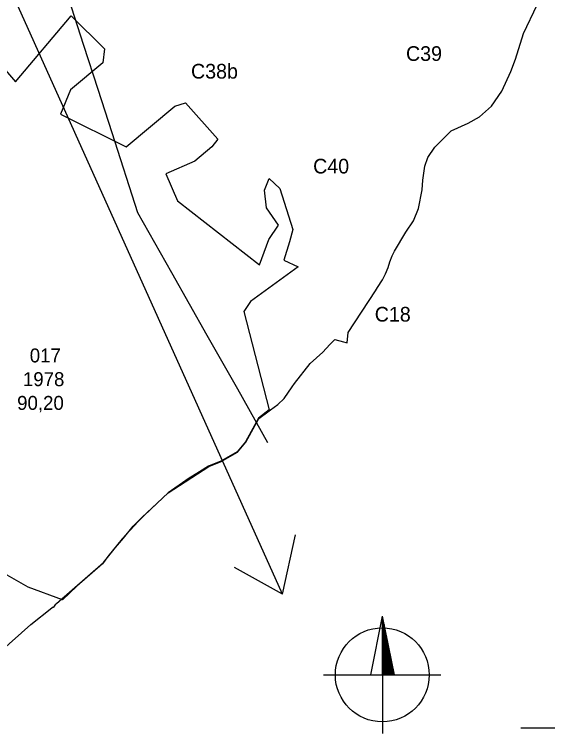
# Model space of a CAD drawing. Extents: x -557103 to -548162, y -1041918 to -1033974.
# Drawn here: x -552210 to -551120, y -1038919 to -1037449 of the extents above; entities that cross this region are included whole.
import ezdxf

# ---------------------------------------------------------------- set-up
doc = ezdxf.new("R2010")
doc.units = 0
for name, color, linetype in [('body3', 7, 'Continuous'), ('Vrstva 14', 7, 'Continuous'), ('Vrstva 15', 7, 'Continuous'), ('Vrstva 37', 7, 'Continuous'), ('Vrstva 48', 7, 'Continuous'), ('Vrstva 57', 7, 'Continuous'), ('Vrstva 9', 7, 'Continuous')]:
    doc.layers.add(name, color=color, linetype=linetype)

msp = doc.modelspace()

# ---------------------------------------------------------------- linework, layer by layer
at = {"layer": 'body3'}
for p, q in [((-551169.3, -1037488.5), (-551141.4, -1037429.8)), ((-551185.4, -1037540.5), (-551169.3, -1037488.5)), ((-551194.9, -1037566.1), (-551185.4, -1037540.5)), ((-551213.2, -1037606.2), (-551194.9, -1037566.1)), ((-551234.2, -1037636.8), (-551213.2, -1037606.2)), ((-551259, -1037658.6), (-551234.2, -1037636.8)), ((-551282, -1037671.4), (-551259, -1037658.6)), ((-551317, -1037686.9), (-551282, -1037671.4)), ((-551350.7, -1037720.5), (-551317, -1037686.9)), ((-551364.5, -1037741.5), (-551350.7, -1037720.5)), ((-551370.6, -1037759.1), (-551364.5, -1037741.5)), ((-551374.7, -1037788.2), (-551370.6, -1037759.1)), ((-551376.2, -1037807.5), (-551374.7, -1037788.2)), ((-551383.6, -1037845.9), (-551376.2, -1037807.5)), ((-551394.1, -1037870.8), (-551383.6, -1037845.9)), ((-551409.7, -1037894), (-551394.1, -1037870.8)), ((-551432.9, -1037932.8), (-551409.7, -1037894)), ((-551437.9, -1037942.3), (-551432.9, -1037932.8)), ((-551445.9, -1037966.2), (-551442.4, -1037954.6)), ((-551442.4, -1037954.6), (-551437.9, -1037942.3)), ((-551451, -1037979.2), (-551445.9, -1037966.2)), ((-551457.2, -1037991.7), (-551451, -1037979.2)), ((-551467.5, -1038007.5), (-551457.2, -1037991.7)), ((-551527.6, -1038099.2), (-551471.9, -1038014.2)), ((-551471.9, -1038014.2), (-551467.5, -1038007.5)), ((-551529.5, -1038120.2), (-551527.6, -1038099.2)), ((-551564.9, -1038123.8), (-551555.1, -1038113.1)), ((-551555.1, -1038113.1), (-551537.3, -1038118)), ((-551537.3, -1038118), (-551532.3, -1038119.4)), ((-551579.4, -1038139.6), (-551564.9, -1038123.8)), ((-551532.3, -1038119.4), (-551529.5, -1038120.2)), ((-551605.4, -1038162.3), (-551579.4, -1038139.6)), ((-551637.2, -1038203.1), (-551605.4, -1038162.3)), ((-551642, -1038210), (-551637.2, -1038203.1)), ((-551658.3, -1038233.8), (-551642, -1038210)), ((-551671.5, -1038246.1), (-551658.3, -1038233.8)), ((-551686.3, -1038257.1), (-551671.5, -1038246.1)), ((-551710.1, -1038274.8), (-551691.9, -1038261.2)), ((-551691.9, -1038261.2), (-551686.3, -1038257.1)), ((-551737, -1038322.9), (-551710.1, -1038274.8)), ((-551753.8, -1038343.5), (-551737, -1038322.9)), ((-551787.2, -1038362.5), (-551753.8, -1038343.5)), ((-551812.7, -1038372.6), (-551787.2, -1038362.5)), ((-551895.6, -1038427), (-551812.7, -1038372.6)), ((-551918.3, -1038448), (-551895.6, -1038427)), ((-551959.9, -1038487.4), (-551918.3, -1038448)), ((-551987.1, -1038519.1), (-551967.4, -1038494.5)), ((-551967.4, -1038494.5), (-551959.9, -1038487.4)), ((-552003.2, -1038538.4), (-551987.1, -1038519.1)), ((-552027.9, -1038569), (-552003.2, -1038538.4)), ((-552124, -1038652.6), (-552027.9, -1038569)), ((-552176.5, -1038695.8), (-552133.3, -1038661.8)), ((-552133.3, -1038661.8), (-552130.6, -1038659.6)), ((-552130.6, -1038659.6), (-552129.5, -1038660.1)), ((-552129.5, -1038660.1), (-552125.2, -1038654.1)), ((-552125.2, -1038654.1), (-552124, -1038652.6)), ((-552240.3, -1038752.1), (-552176.5, -1038695.8))]:
    msp.add_line(p, q, dxfattribs=at)
at = {"layer": 'Vrstva 14'}
for q in [(-551635.1, -1038512.8), (-551760.2, -1038579.1)]:
    msp.add_line((-551661.8, -1038633.9), q, dxfattribs=at)
msp.add_lwpolyline([(-551661.8, -1038633.9), (-553519.6, -1034507.2), (-553504.9, -1034676.5)], dxfattribs=at)
at = {"layer": 'Vrstva 15'}
for points in [[(-552068.1, -1037512.6), (-552118.7, -1037355.6), (-552166.5, -1037207.2), (-552210.9, -1037069.8), (-552249.3, -1036951.7), (-552280.1, -1036856.3), (-552310.8, -1036764.1)], [(-551691.6, -1038324.2), (-551753.3, -1038215.2), (-551815.6, -1038104.9), (-551888, -1037977.1), (-551957.3, -1037854.4), (-552010.3, -1037691.4), (-552039, -1037602.4), (-552068.1, -1037512.6)]]:
    msp.add_lwpolyline(points, dxfattribs=at)
at = {"layer": 'Vrstva 48'}
msp.add_line((-551174.3, -1038906.8), (-550963.1, -1038906.8), dxfattribs=at)
at = {"layer": 'Vrstva 57'}
for p, q in [((-551457.9, -1038678.6), (-551481.8, -1038798.6)), ((-551457.9, -1038678.6), (-551457.7, -1038918.6)), ((-551457.9, -1038678.6), (-551433.8, -1038798.6)), ((-551456.7, -1038683.8), (-551456.6, -1038798.6)), ((-551455.5, -1038690.9), (-551455.4, -1038798.6)), ((-551454.3, -1038695.8), (-551454.2, -1038798.6)), ((-551453.1, -1038702.9), (-551453, -1038798.6)), ((-551451.9, -1038708.3), (-551451.8, -1038798.6)), ((-551450.7, -1038714.7), (-551450.6, -1038798.6)), ((-551449.5, -1038719.9), (-551449.4, -1038798.6)), ((-551448.3, -1038728.2), (-551448.2, -1038798.6)), ((-551447.1, -1038732.7), (-551447, -1038798.6)), ((-551445.9, -1038738.5), (-551445.8, -1038798.6)), ((-551444.7, -1038744.3), (-551444.6, -1038798.6)), ((-551443.5, -1038750.6), (-551443.4, -1038798.6)), ((-551442.3, -1038756.6), (-551442.2, -1038798.6)), ((-551441.1, -1038762.8), (-551441, -1038798.6)), ((-551439.8, -1038769), (-551439.8, -1038798.6)), ((-551438.6, -1038774.4), (-551438.6, -1038798.6)), ((-551437.4, -1038780.4), (-551437.4, -1038798.6)), ((-551436.2, -1038786.6), (-551436.2, -1038798.6)), ((-551435, -1038791.8), (-551435, -1038798.6)), ((-551577.8, -1038798.7), (-551337.8, -1038798.5))]:
    msp.add_line(p, q, dxfattribs=at)
msp.add_circle((-551457.8, -1038798.6), 96, dxfattribs=at)
at = {"layer": 'Vrstva 9'}
msp.add_lwpolyline([(-552244.4, -1037544.4), (-552207.6, -1037586.8), (-552094, -1037452.1), (-552025.6, -1037519.4), (-552029.1, -1037548.3), (-552095.4, -1037603.5), (-552115.6, -1037653.2), (-551981.3, -1037719.5), (-551881.9, -1037636.6), (-551859.9, -1037629.6), (-551793.8, -1037703.8), (-551806.4, -1037719.5), (-551841.4, -1037748.9), (-551900.3, -1037774.7), (-551876.4, -1037829.9), (-551708.9, -1037960.6), (-551690.1, -1037909.4), (-551669.8, -1037879.9), (-551694.7, -1037844.4), (-551698.7, -1037808.4), (-551689.3, -1037784.3), (-551667.2, -1037804.6), (-551640.8, -1037888.8), (-551647.3, -1037914.1), (-551658.8, -1037951.1), (-551629.8, -1037965), (-551727.2, -1038035.7), (-551741.1, -1038056.5), (-551689.2, -1038257.3), (-551711, -1038273.8), (-551737.7, -1038322.6), (-551754.7, -1038342.6), (-551787.8, -1038362), (-551812.9, -1038372.1), (-551836.8, -1038387.5), (-551852.4, -1038396.9), (-551895.4, -1038426.9), (-551918.4, -1038447.7), (-551948.8, -1038476.2), (-551989.9, -1038520.8), (-552018.7, -1038556.9), (-552029.8, -1038571.8), (-552082.2, -1038617.7), (-552111.9, -1038645.2), (-552181.9, -1038619.5), (-552301.5, -1038551.3)], dxfattribs=at)

# ---------------------------------------------------------------- texts
at = {"layer": 'Vrstva 37'}
for s, p in [('C39', (-551409.3, -1037544.2)), ('C38b', (-551848.9, -1037580.3)), ('C40', (-551599.2, -1037774.2)), ('C18', (-551473.2, -1038076.8))]:
    msp.add_text(s, height=30, dxfattribs=at).set_placement(p)
at = {"layer": 'Vrstva 9'}
for s, p in [('017', (-552178.6, -1038160.2)), ('1978', (-552192.6, -1038208.7)), ('90,20', (-552204.4, -1038257.2))]:
    msp.add_text(s, height=28.5, dxfattribs=at).set_placement(p)

doc.saveas('drawing.dxf')
